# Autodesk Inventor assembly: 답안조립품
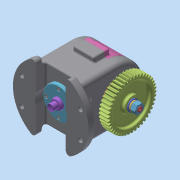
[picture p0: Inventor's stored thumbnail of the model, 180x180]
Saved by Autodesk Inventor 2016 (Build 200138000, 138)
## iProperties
Created: 2024-08
Part Number: 답안조립품
Material: 일반
Document SubType Name: Assembly
Designer: pc-2
Author: pc-2
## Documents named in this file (21)
- C:\Users\pc-2\Desktop\740804V1018\답안조립품.iam
- C:\Users\pc-2\Desktop\740804V1018\1.ipt
- C:\Users\pc-2\Documents\Inventor\깊은 홈 볼 베어링 6904.ipt
- C:\Users\pc-2\Desktop\740804V1018\가져온 구성요소\뒷커버\뒷커버.ipt
- C:\Users\pc-2\Desktop\740804V1018\가져온 구성요소\링크\링크.ipt
- C:\Users\pc-2\Desktop\740804V1018\가져온 구성요소\부시 커버\부시 커버.ipt
- C:\Users\pc-2\Desktop\740804V1018\가져온 구성요소\스퍼 기어\스퍼 기어.ipt
- C:\Users\pc-2\Desktop\740804V1018\가져온 구성요소\스프링 와셔 M10\스프링 와셔 M10.ipt
- C:\Users\pc-2\Desktop\740804V1018\가져온 구성요소\앞커버\앞커버.ipt
- C:\Users\pc-2\Desktop\740804V1018\가져온 구성요소\오일레스 부시 20 15\오일레스 부시 20 15.ipt
- C:\Users\pc-2\Desktop\740804V1018\가져온 구성요소\오일실 20 32 5\오일실 20 32 5.ipt
- C:\Users\pc-2\Desktop\740804V1018\가져온 구성요소\윗커버\윗커버.ipt
- C:\Users\pc-2\Desktop\740804V1018\가져온 구성요소\육각 너트 M10x1\육각 너트 M10x1.ipt
- C:\Users\pc-2\Desktop\740804V1018\가져온 구성요소\육각 소켓 머리 볼트 M4x10\육각 소켓 머리 볼트 M4x10.ipt
- C:\Users\pc-2\Desktop\740804V1018\가져온 구성요소\칼라\칼라.ipt
- C:\Users\pc-2\Desktop\740804V1018\가져온 구성요소\펀치\펀치.ipt
- C:\Users\pc-2\Desktop\740804V1018\가져온 구성요소\편심축\편심축.ipt
- C:\Users\pc-2\Desktop\740804V1018\가져온 구성요소\평와셔 M10\평와셔 M10.ipt
- C:\Users\pc-2\Desktop\740804V1018\가져온 구성요소\평행키 5x5x12\평행키 5x5x12.ipt
- C:\Users\pc-2\Desktop\740804V1018\가져온 구성요소\핀\핀.ipt
- C:\Users\pc-2\Desktop\740804V1018\가져온 구성요소\E형 멈춤링 10-8\E형 멈춤링 10-8.ipt
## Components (3 placed, 3 different names)
1. 1:1 — 각도:1
2. 핀:1
3. E형 멈춤링 10-8:1
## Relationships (1: Angle 1)
- 각도:1 [Angle]: 1:1
